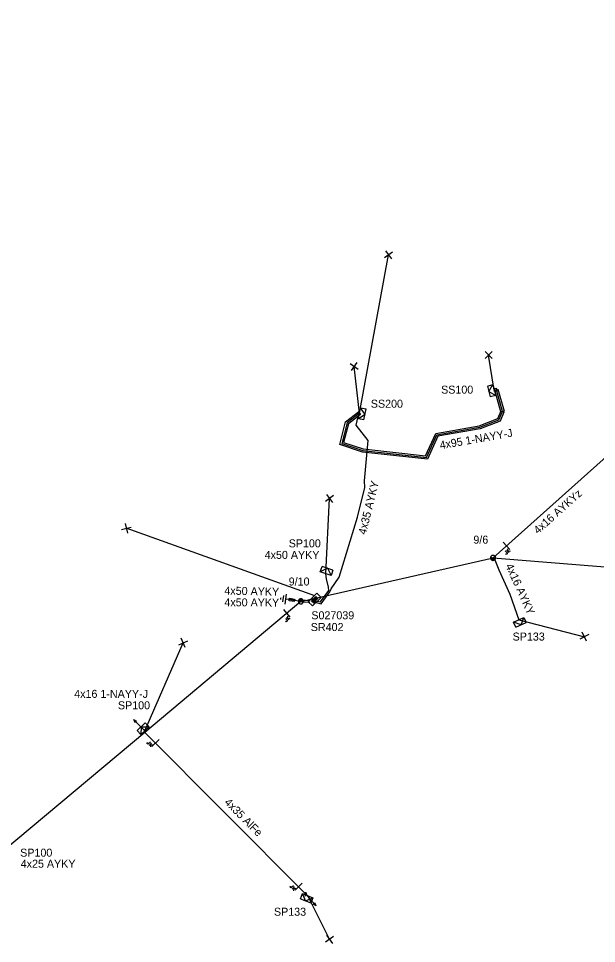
# Model space of a CAD drawing. Extents: x -788458 to -786145, y -1154772 to -1152372.
# Drawn here: x -786525 to -786452.8, y -1153561.6 to -1153446 of the extents above; entities that cross this region are included whole.
import ezdxf

# ---------------------------------------------------------------- set-up
doc = ezdxf.new("R2010")
doc.units = 0
for name, color, linetype in [('Vrstva 1', 7, 'Continuous'), ('Vrstva 12', 7, 'Continuous'), ('Vrstva 13', 7, 'Continuous'), ('Vrstva 14', 7, 'Continuous'), ('Vrstva 15', 7, 'Continuous'), ('Vrstva 16', 7, 'Continuous'), ('Vrstva 18', 7, 'Continuous'), ('Vrstva 2', 7, 'Continuous'), ('Vrstva 20', 7, 'Continuous'), ('Vrstva 28', 7, 'Continuous'), ('Vrstva 29', 7, 'Continuous'), ('Vrstva 30', 7, 'Continuous'), ('Vrstva 31', 7, 'Continuous'), ('Vrstva 33', 7, 'Continuous'), ('Vrstva 34', 7, 'Continuous'), ('Vrstva 4', 7, 'Continuous'), ('Vrstva 5', 7, 'Continuous'), ('Vrstva 52', 7, 'Continuous'), ('Vrstva 53', 7, 'Continuous'), ('Vrstva 54', 7, 'Continuous'), ('Vrstva 55', 7, 'Continuous'), ('Vrstva 59', 7, 'Continuous'), ('Vrstva 6', 7, 'Continuous'), ('Vrstva 8', 7, 'Continuous'), ('Vrstva 9', 7, 'Continuous')]:
    doc.layers.add(name, color=color, linetype=linetype)

# ---------------------------------------------------------------- blocks, each defined once
blk = doc.blocks.new('NN440')
at = {"layer": 'Vrstva 2'}
for points in [[(0.63, 0), (0.63, 0.06), (0.62, 0.13), (0.6, 0.19), (0.58, 0.25), (0.55, 0.31), (0.51, 0.37), (0.47, 0.42), (0.42, 0.46), (0.37, 0.51), (0.32, 0.54), (0.26, 0.57), (0.2, 0.59), (0.13, 0.61), (0.07, 0.62), (0, 0.63), (-0.06, 0.62), (-0.13, 0.61), (-0.19, 0.59), (-0.26, 0.57), (-0.31, 0.54), (-0.37, 0.51), (-0.42, 0.46), (-0.47, 0.42), (-0.51, 0.37), (-0.54, 0.31), (-0.57, 0.25), (-0.6, 0.19), (-0.62, 0.13), (-0.63, 0.06), (-0.63, 0), (-0.63, -0.07), (-0.62, -0.14), (-0.6, -0.2), (-0.57, -0.26), (-0.54, -0.32), (-0.51, -0.37), (-0.47, -0.43), (-0.42, -0.47), (-0.37, -0.51), (-0.31, -0.55), (-0.26, -0.58), (-0.19, -0.6), (-0.13, -0.62), (-0.06, -0.63), (0, -0.63), (0.07, -0.63), (0.13, -0.62), (0.2, -0.6), (0.26, -0.58), (0.32, -0.55), (0.37, -0.51), (0.42, -0.47), (0.47, -0.43), (0.51, -0.37), (0.55, -0.32), (0.58, -0.26), (0.6, -0.2), (0.62, -0.14), (0.63, -0.07), (0.63, 0)], [(-0.63, 0), (0.63, 0)], [(-0.6, -0.18), (0.57, -0.18)], [(-0.51, -0.32), (0.5, -0.32)], [(-0.37, -0.47), (0.35, -0.47)]]:
    blk.add_lwpolyline(points, dxfattribs=at)
blk = doc.blocks.new('NN560')
at = {"layer": 'Vrstva 2'}
for points in [[(2, 0), (1.59, 0.14)], [(0, 0), (2, 0)], [(2, 0), (1.59, -0.13)]]:
    blk.add_lwpolyline(points, dxfattribs=at)
blk = doc.blocks.new('NN840')
at = {"layer": 'Vrstva 15'}
for points in [[(0, 0.62), (0, -0.63)], [(-0.75, -0.71), (-0.75, -0.66)], [(-0.73, -0.76), (-0.75, -0.71)], [(-0.66, -0.8), (-0.73, -0.76)], [(-0.63, -0.8), (-0.66, -0.8)], [(-0.56, -0.76), (-0.63, -0.8)], [(-0.54, -0.71), (-0.56, -0.76)], [(-0.54, -0.38), (-0.54, -0.71)], [(-0.33, -0.38), (-0.33, -0.8)], [(-0.33, -0.64), (-0.13, -0.38)], [(-0.26, -0.56), (-0.09, -0.8)]]:
    blk.add_lwpolyline(points, dxfattribs=at)
blk = doc.blocks.new('NN800')
at = {"layer": 'Vrstva 1'}
for points in [[(-0.44, 0.44), (0.44, -0.44)], [(-0.44, -0.44), (0.44, 0.44)]]:
    blk.add_lwpolyline(points, dxfattribs=at)
blk = doc.blocks.new('NN820')
at = {"layer": 'Vrstva 13'}
for points in [[(0, 0), (0, -1.05)], [(-0.16, -0.81), (0.16, -0.81)], [(-0.16, -1.47), (-0.16, -0.81)], [(0, -1.05), (-0.06, -0.93)], [(0, -1.05), (0.06, -0.93)], [(0.16, -0.81), (0.16, -1.47)], [(0.16, -1.47), (-0.16, -1.47)], [(0, -1.47), (0, -1.87)]]:
    blk.add_lwpolyline(points, dxfattribs=at)
blk = doc.blocks.new('NN620')
at = {"layer": 'Vrstva 8'}
for points in [[(0.75, 0), (-0.75, 0)], [(-0.75, 0), (-0.75, -0.75)], [(0.75, -0.75), (0.75, 0)], [(-0.75, -0.75), (0.75, -0.75)], [(0.37, -0.18), (-0.38, -0.18)], [(-0.38, -0.18), (-0.38, -0.56)], [(-0.38, -0.56), (0.37, -0.56)], [(0.32, -0.23), (-0.33, -0.23)], [(-0.33, -0.23), (-0.33, -0.51)], [(-0.33, -0.51), (0.32, -0.51)], [(0.27, -0.27), (-0.28, -0.27)], [(-0.28, -0.27), (-0.28, -0.46)], [(-0.28, -0.46), (0.27, -0.46)], [(0.23, -0.32), (-0.23, -0.32)], [(-0.23, -0.32), (-0.23, -0.42)], [(-0.23, -0.42), (0.23, -0.42)], [(-0.19, -0.37), (0.19, -0.37)], [(0.23, -0.42), (0.23, -0.32)], [(0.27, -0.46), (0.27, -0.27)], [(0.32, -0.51), (0.32, -0.23)], [(0.37, -0.56), (0.37, -0.18)]]:
    blk.add_lwpolyline(points, dxfattribs=at)
blk = doc.blocks.new('NN630')
at = {"layer": 'Vrstva 9'}
for points in [[(0, -0.7), (-0.7, 0)], [(-0.7, -0.7), (-0.7, 0), (0.7, 0), (0.7, -0.7)], [(-0.7, -0.7), (0.7, -0.7)], [(0, -0.7), (0.7, 0)]]:
    blk.add_lwpolyline(points, dxfattribs=at)
blk = doc.blocks.new('NN810')
at = {"layer": 'Vrstva 14'}
for points in [[(0, -0.64), (0, -1.89)], [(0.63, -1.89), (-0.62, -1.89)], [(0.39, -2.2), (-0.4, -2.2)], [(0, -2.52), (-0.12, -2.52)], [(0.14, -2.52), (0, -2.52)]]:
    blk.add_lwpolyline(points, dxfattribs=at)
blk = doc.blocks.new('NN500')
at = {"layer": 'Vrstva 2'}
for points in [[(0, -0.24), (0.02, -0.23), (0.05, -0.23), (0.07, -0.22), (0.09, -0.22), (0.12, -0.2), (0.14, -0.19), (0.16, -0.18), (0.17, -0.16), (0.19, -0.14), (0.2, -0.12), (0.21, -0.1), (0.22, -0.07), (0.23, -0.05), (0.23, -0.02), (0.23, 0), (0.23, 0.02), (0.23, 0.05), (0.22, 0.07), (0.21, 0.1), (0.2, 0.12), (0.19, 0.14), (0.17, 0.16), (0.16, 0.17), (0.14, 0.19), (0.12, 0.2), (0.09, 0.21), (0.07, 0.22), (0.05, 0.23), (0.02, 0.23), (0, 0.23), (-0.03, 0.23), (-0.05, 0.23), (-0.07, 0.22), (-0.1, 0.21), (-0.12, 0.2), (-0.14, 0.19), (-0.16, 0.17), (-0.18, 0.16), (-0.19, 0.14), (-0.2, 0.12), (-0.22, 0.1), (-0.22, 0.07), (-0.23, 0.05), (-0.23, 0.02), (-0.24, 0), (-0.23, -0.02), (-0.23, -0.05), (-0.22, -0.07), (-0.22, -0.1), (-0.2, -0.12), (-0.19, -0.14), (-0.18, -0.16), (-0.16, -0.18), (-0.14, -0.19), (-0.12, -0.2), (-0.1, -0.22), (-0.07, -0.22), (-0.05, -0.23), (-0.03, -0.23), (0, -0.24)], [(0, -0.24), (0.02, -0.23), (0.05, -0.23), (0.07, -0.22), (0.09, -0.22), (0.12, -0.2), (0.14, -0.19), (0.16, -0.18), (0.17, -0.16), (0.19, -0.14), (0.2, -0.12), (0.21, -0.1), (0.22, -0.07), (0.23, -0.05), (0.23, -0.02), (0.23, 0), (0.23, 0.02), (0.23, 0.05), (0.22, 0.07), (0.21, 0.1), (0.2, 0.12), (0.19, 0.14), (0.17, 0.16), (0.16, 0.17), (0.14, 0.19), (0.12, 0.2), (0.09, 0.21), (0.07, 0.22), (0.05, 0.23), (0.02, 0.23), (0, 0.23), (-0.03, 0.23), (-0.05, 0.23), (-0.07, 0.22), (-0.1, 0.21), (-0.12, 0.2), (-0.14, 0.19), (-0.16, 0.17), (-0.18, 0.16), (-0.19, 0.14), (-0.2, 0.12), (-0.22, 0.1), (-0.22, 0.07), (-0.23, 0.05), (-0.23, 0.02), (-0.24, 0), (-0.23, -0.02), (-0.23, -0.05), (-0.22, -0.07), (-0.22, -0.1), (-0.2, -0.12), (-0.19, -0.14), (-0.18, -0.16), (-0.16, -0.18), (-0.14, -0.19), (-0.12, -0.2), (-0.1, -0.22), (-0.07, -0.22), (-0.05, -0.23), (-0.03, -0.23), (0, -0.24)], [(0, -0.21), (0.02, -0.2), (0.04, -0.2), (0.06, -0.2), (0.08, -0.19), (0.1, -0.18), (0.12, -0.17), (0.14, -0.15), (0.15, -0.14), (0.16, -0.12), (0.18, -0.1), (0.19, -0.08), (0.19, -0.06), (0.2, -0.04), (0.2, -0.02), (0.2, 0), (0.2, 0.02), (0.2, 0.04), (0.19, 0.06), (0.19, 0.08), (0.18, 0.1), (0.16, 0.12), (0.15, 0.14), (0.14, 0.15), (0.12, 0.17), (0.1, 0.18), (0.08, 0.19), (0.06, 0.19), (0.04, 0.2), (0.02, 0.2), (0, 0.2), (-0.02, 0.2), (-0.04, 0.2), (-0.06, 0.19), (-0.08, 0.19), (-0.1, 0.18), (-0.12, 0.17), (-0.14, 0.15), (-0.15, 0.14), (-0.17, 0.12), (-0.18, 0.1), (-0.19, 0.08), (-0.2, 0.06), (-0.2, 0.04), (-0.21, 0.02), (-0.21, 0), (-0.21, -0.02), (-0.2, -0.04), (-0.2, -0.06), (-0.19, -0.08), (-0.18, -0.1), (-0.17, -0.12), (-0.15, -0.14), (-0.14, -0.15), (-0.12, -0.17), (-0.1, -0.18), (-0.08, -0.19), (-0.06, -0.2), (-0.04, -0.2), (-0.02, -0.2), (0, -0.21)], [(0, -0.18), (0.02, -0.18), (0.04, -0.17), (0.05, -0.17), (0.07, -0.16), (0.09, -0.15), (0.1, -0.14), (0.12, -0.13), (0.13, -0.12), (0.14, -0.1), (0.15, -0.09), (0.16, -0.07), (0.17, -0.05), (0.17, -0.04), (0.17, -0.02), (0.17, 0), (0.17, 0.02), (0.17, 0.04), (0.17, 0.05), (0.16, 0.07), (0.15, 0.09), (0.14, 0.1), (0.13, 0.12), (0.12, 0.13), (0.1, 0.14), (0.09, 0.15), (0.07, 0.16), (0.05, 0.17), (0.04, 0.17), (0.02, 0.17), (0, 0.18), (-0.02, 0.17), (-0.04, 0.17), (-0.06, 0.17), (-0.07, 0.16), (-0.09, 0.15), (-0.1, 0.14), (-0.12, 0.13), (-0.13, 0.12), (-0.14, 0.1), (-0.15, 0.09), (-0.16, 0.07), (-0.17, 0.05), (-0.17, 0.04), (-0.18, 0.02), (-0.18, 0), (-0.18, -0.02), (-0.17, -0.04), (-0.17, -0.05), (-0.16, -0.07), (-0.15, -0.09), (-0.14, -0.1), (-0.13, -0.12), (-0.12, -0.13), (-0.1, -0.14), (-0.09, -0.15), (-0.07, -0.16), (-0.06, -0.17), (-0.04, -0.17), (-0.02, -0.18), (0, -0.18)], [(0, -0.15), (0.01, -0.15), (0.03, -0.14), (0.04, -0.14), (0.06, -0.13), (0.07, -0.13), (0.08, -0.12), (0.1, -0.11), (0.11, -0.1), (0.12, -0.09), (0.13, -0.07), (0.13, -0.06), (0.14, -0.05), (0.14, -0.03), (0.14, -0.02), (0.14, 0), (0.14, 0.01), (0.14, 0.03), (0.14, 0.04), (0.13, 0.06), (0.13, 0.07), (0.12, 0.09), (0.11, 0.1), (0.1, 0.11), (0.08, 0.12), (0.07, 0.13), (0.06, 0.13), (0.04, 0.14), (0.03, 0.14), (0.01, 0.14), (0, 0.15), (-0.02, 0.14), (-0.03, 0.14), (-0.05, 0.14), (-0.06, 0.13), (-0.07, 0.13), (-0.09, 0.12), (-0.1, 0.11), (-0.11, 0.1), (-0.12, 0.09), (-0.13, 0.07), (-0.13, 0.06), (-0.14, 0.04), (-0.14, 0.03), (-0.15, 0.01), (-0.15, 0), (-0.15, -0.02), (-0.14, -0.03), (-0.14, -0.05), (-0.13, -0.06), (-0.13, -0.07), (-0.12, -0.09), (-0.11, -0.1), (-0.1, -0.11), (-0.09, -0.12), (-0.07, -0.13), (-0.06, -0.13), (-0.05, -0.14), (-0.03, -0.14), (-0.02, -0.15), (0, -0.15)], [(0, -0.12), (0.01, -0.12), (0.02, -0.11), (0.03, -0.11), (0.05, -0.11), (0.06, -0.1), (0.07, -0.09), (0.08, -0.09), (0.09, -0.08), (0.09, -0.07), (0.1, -0.06), (0.11, -0.05), (0.11, -0.04), (0.11, -0.02), (0.11, -0.01), (0.12, 0), (0.11, 0.01), (0.11, 0.02), (0.11, 0.04), (0.11, 0.05), (0.1, 0.06), (0.09, 0.07), (0.09, 0.08), (0.08, 0.09), (0.07, 0.09), (0.06, 0.1), (0.05, 0.11), (0.03, 0.11), (0.02, 0.11), (0.01, 0.12), (0, 0.12), (-0.01, 0.12), (-0.03, 0.11), (-0.04, 0.11), (-0.05, 0.11), (-0.06, 0.1), (-0.07, 0.09), (-0.08, 0.09), (-0.09, 0.08), (-0.1, 0.07), (-0.1, 0.06), (-0.11, 0.05), (-0.11, 0.04), (-0.12, 0.02), (-0.12, 0.01), (-0.12, 0), (-0.12, -0.01), (-0.12, -0.02), (-0.11, -0.04), (-0.11, -0.05), (-0.1, -0.06), (-0.1, -0.07), (-0.09, -0.08), (-0.08, -0.09), (-0.07, -0.09), (-0.06, -0.1), (-0.05, -0.11), (-0.04, -0.11), (-0.03, -0.11), (-0.01, -0.12), (0, -0.12)], [(0, -0.09), (0.01, -0.09), (0.02, -0.09), (0.03, -0.08), (0.03, -0.08), (0.04, -0.08), (0.05, -0.07), (0.06, -0.07), (0.06, -0.06), (0.07, -0.05), (0.07, -0.04), (0.08, -0.04), (0.08, -0.03), (0.08, -0.02), (0.09, -0.01), (0.09, 0), (0.09, 0.01), (0.08, 0.02), (0.08, 0.03), (0.08, 0.03), (0.07, 0.04), (0.07, 0.05), (0.06, 0.06), (0.06, 0.06), (0.05, 0.07), (0.04, 0.07), (0.03, 0.08), (0.03, 0.08), (0.02, 0.08), (0.01, 0.09), (0, 0.09), (-0.01, 0.09), (-0.02, 0.08), (-0.03, 0.08), (-0.04, 0.08), (-0.04, 0.07), (-0.05, 0.07), (-0.06, 0.06), (-0.07, 0.06), (-0.07, 0.05), (-0.08, 0.04), (-0.08, 0.03), (-0.08, 0.03), (-0.09, 0.02), (-0.09, 0.01), (-0.09, 0), (-0.09, -0.01), (-0.09, -0.02), (-0.08, -0.03), (-0.08, -0.04), (-0.08, -0.04), (-0.07, -0.05), (-0.07, -0.06), (-0.06, -0.07), (-0.05, -0.07), (-0.04, -0.08), (-0.04, -0.08), (-0.03, -0.08), (-0.02, -0.09), (-0.01, -0.09), (0, -0.09)], [(0, -0.06), (0, -0.06), (0.01, -0.06), (0.02, -0.05), (0.02, -0.05), (0.03, -0.05), (0.03, -0.05), (0.04, -0.04), (0.04, -0.04), (0.05, -0.03), (0.05, -0.03), (0.05, -0.02), (0.05, -0.02), (0.05, -0.01), (0.06, -0.01), (0.06, 0), (0.06, 0.01), (0.05, 0.01), (0.05, 0.02), (0.05, 0.02), (0.05, 0.03), (0.05, 0.03), (0.04, 0.04), (0.04, 0.04), (0.03, 0.05), (0.03, 0.05), (0.02, 0.05), (0.02, 0.05), (0.01, 0.06), (0, 0.06), (0, 0.06), (-0.01, 0.06), (-0.01, 0.06), (-0.02, 0.05), (-0.02, 0.05), (-0.03, 0.05), (-0.03, 0.05), (-0.04, 0.04), (-0.04, 0.04), (-0.05, 0.03), (-0.05, 0.03), (-0.05, 0.02), (-0.06, 0.02), (-0.06, 0.01), (-0.06, 0.01), (-0.06, 0), (-0.06, -0.01), (-0.06, -0.01), (-0.06, -0.02), (-0.05, -0.02), (-0.05, -0.03), (-0.05, -0.03), (-0.04, -0.04), (-0.04, -0.04), (-0.03, -0.05), (-0.03, -0.05), (-0.02, -0.05), (-0.02, -0.05), (-0.01, -0.06), (-0.01, -0.06), (0, -0.06)], [(0, -0.03), (0, -0.03), (0, -0.03), (0.01, -0.03), (0.01, -0.03), (0.01, -0.02), (0.02, -0.02), (0.02, -0.02), (0.02, -0.02), (0.02, -0.02), (0.02, -0.01), (0.02, -0.01), (0.03, -0.01), (0.03, -0.01), (0.03, 0), (0.03, 0), (0.03, 0), (0.03, 0.01), (0.03, 0.01), (0.02, 0.01), (0.02, 0.01), (0.02, 0.02), (0.02, 0.02), (0.02, 0.02), (0.02, 0.02), (0.01, 0.02), (0.01, 0.02), (0.01, 0.03), (0, 0.03), (0, 0.03), (0, 0.03), (0, 0.03), (-0.01, 0.03), (-0.01, 0.03), (-0.01, 0.02), (-0.02, 0.02), (-0.02, 0.02), (-0.02, 0.02), (-0.02, 0.02), (-0.02, 0.02), (-0.03, 0.01), (-0.03, 0.01), (-0.03, 0.01), (-0.03, 0.01), (-0.03, 0), (-0.03, 0), (-0.03, 0), (-0.03, -0.01), (-0.03, -0.01), (-0.03, -0.01), (-0.03, -0.01), (-0.02, -0.02), (-0.02, -0.02), (-0.02, -0.02), (-0.02, -0.02), (-0.02, -0.02), (-0.01, -0.03), (-0.01, -0.03), (-0.01, -0.03), (0, -0.03), (0, -0.03)], [(0.23, 0), (0.7, 0)]]:
    blk.add_lwpolyline(points, dxfattribs=at)

msp = doc.modelspace()

# ---------------------------------------------------------------- linework, layer by layer
at = {"layer": 'Vrstva 1'}
for points in [[(-786489.69, -1153518.84), (-786509.16, -1153535.21), (-786526.82, -1153550.01), (-786583.29, -1153546.79), (-786577.19, -1153510.6), (-786570.4, -1153472.16), (-786563.85, -1153433.39), (-786557.73, -1153395.36), (-786551.92, -1153358.3), (-786545.97, -1153321.74)], [(-786489.69, -1153518.84), (-786465.68, -1153513.4), (-786435.17, -1153515.87), (-786408.35, -1153517.77)]]:
    msp.add_lwpolyline(points, dxfattribs=at)
at = {"layer": 'Vrstva 20'}
for points in [[(-786465.56, -1153492.23), (-786465.29, -1153492.19), (-786465.23, -1153492.59), (-786465.5, -1153492.63)], [(-786464.69, -1153495.15), (-786465.45, -1153492.44), (-786465.07, -1153492.34), (-786464.31, -1153495.05)], [(-786482.24, -1153495.49), (-786483.74, -1153496.66), (-786484.35, -1153498.99), (-786481.92, -1153499.79), (-786474.12, -1153500.64), (-786472.85, -1153497.85), (-786467.4, -1153496.9), (-786465.1, -1153495.98), (-786464.68, -1153495.02), (-786464.32, -1153495.18), (-786464.8, -1153496.3), (-786467.3, -1153497.28), (-786472.57, -1153498.21), (-786473.88, -1153501.06), (-786482, -1153500.19), (-786484.83, -1153499.25), (-786484.1, -1153496.42), (-786482.48, -1153495.17)]]:
    msp.add_lwpolyline(points, close=True, dxfattribs=at)
at = {"layer": 'Vrstva 4'}
msp.add_lwpolyline([(-786509.16, -1153535.21), (-786489.09, -1153555.38), (-786488.84, -1153555.62)], dxfattribs=at)
at = {"layer": 'Vrstva 5'}
for points in [[(-786482.36, -1153495.33), (-786483.92, -1153496.54), (-786484.59, -1153499.12), (-786481.96, -1153499.99), (-786474, -1153500.85), (-786472.71, -1153498.03), (-786467.35, -1153497.09), (-786464.95, -1153496.14), (-786464.5, -1153495.1), (-786465.26, -1153492.39), (-786465.53, -1153492.43)], [(-786487.78, -1153518.97), (-786487.15, -1153519.13), (-786486.07, -1153517.66), (-786485.91, -1153517.26), (-786484.92, -1153515.82), (-786482.61, -1153508.3), (-786481.7, -1153504.6), (-786481.72, -1153503.79), (-786481.29, -1153498.73), (-786482.8, -1153496.82), (-786482.55, -1153495.74), (-786482.36, -1153495.33)], [(-786488.53, -1153518.77), (-786489.12, -1153518.75), (-786489.55, -1153518.73), (-786489.69, -1153518.84)], [(-786488.58, -1153518.97), (-786489.53, -1153518.94), (-786489.69, -1153518.84)]]:
    msp.add_lwpolyline(points, dxfattribs=at)
at = {"layer": 'Vrstva 52'}
for points in [[(-786465.68, -1153513.4), (-786465.45, -1153513.65), (-786464.96, -1153514.88), (-786463.58, -1153517.93), (-786462.48, -1153521.15)], [(-786487.62, -1153518.81), (-786487.23, -1153518.91), (-786486.18, -1153517.47), (-786486.25, -1153517.08), (-786486.47, -1153516.01), (-786486.59, -1153515.38)]]:
    msp.add_lwpolyline(points, dxfattribs=at)
at = {"layer": 'Vrstva 54'}
msp.add_lwpolyline([(-786465.68, -1153513.4), (-786449.16, -1153498.66), (-786449, -1153498.89)], dxfattribs=at)
at = {"layer": 'Vrstva 59'}
for points in [[(-786482.36, -1153495.33), (-786478.75, -1153475.55)], [(-786465.53, -1153492.43), (-786466.24, -1153488.06)], [(-786482.36, -1153495.33), (-786483.05, -1153489.47)], [(-786486.59, -1153515.38), (-786486.12, -1153505.99)], [(-786487.93, -1153518.17), (-786511.5, -1153509.71)], [(-786462.48, -1153521.15), (-786454.28, -1153523.26)], [(-786509.16, -1153535.01), (-786504.38, -1153524.02)], [(-786488.84, -1153555.62), (-786486.11, -1153561.09)]]:
    msp.add_lwpolyline(points, dxfattribs=at)
at = {"layer": 'Vrstva 8'}
msp.add_lwpolyline([(-786509.16, -1153535.21), (-786509.16, -1153535.01)], dxfattribs=at)

# ---------------------------------------------------------------- block references
at = {"layer": 'Vrstva 13', "yscale": 0.5}
for name, p, xscale, rotation in [('NN440', (-786465.68, -1153513.4), 0.5, -13.829819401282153), ('NN440', (-786489.69, -1153518.84), 0.5, -142.00139163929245), ('NN500', (-786509.16, -1153535.01), 0.5, 136.7389999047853), ('NN500', (-786489.09, -1153555.38), 0.49999999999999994, -107.399000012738)]:
    msp.add_blockref(name, p, dxfattribs=dict(at, xscale=xscale, rotation=rotation))
at = {"layer": 'Vrstva 13'}
for p, rotation in [((-786509.16, -1153535.01), 135.71013331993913), ((-786489.09, -1153555.38), -49.68320555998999)]:
    msp.add_blockref('NN560', p, dxfattribs=dict(at, rotation=rotation))
at = {"layer": 'Vrstva 15', "rotation": -98.69812771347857}
msp.add_blockref('NN810', (-786489.69, -1153518.84), dxfattribs=at)
at = {"layer": 'Vrstva 16', "rotation": -98.69922221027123}
msp.add_blockref('NN820', (-786489.69, -1153518.84), dxfattribs=at)
at = {"layer": 'Vrstva 18'}
for p, rotation in [((-786464, -1153511.9), 41.74099578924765), ((-786491.46, -1153520.33), 40.0564745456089), ((-786507.84, -1153536.54), -45.14238484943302), ((-786489.97, -1153554.5), -45.14238484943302)]:
    msp.add_blockref('NN840', p, dxfattribs=dict(at, rotation=rotation))
at = {"layer": 'Vrstva 28', "rotation": -135}
msp.add_blockref('NN620', (-786487.7, -1153518.89), dxfattribs=at)
at = {"layer": 'Vrstva 31'}
for p, rotation in [((-786465.53, -1153492.43), -75.59778379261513), ((-786482.36, -1153495.33), 78.66098919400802), ((-786486.59, -1153515.38), 162.40757535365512), ((-786462.48, -1153521.15), 24.63011890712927), ((-786509.16, -1153535.01), -136.10881209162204), ((-786488.84, -1153555.62), -21.729789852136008)]:
    msp.add_blockref('NN630', p, dxfattribs=dict(at, rotation=rotation))
at = {"layer": 'Vrstva 34'}
for p, rotation in [((-786478.75, -1153475.55), -98.71133333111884), ((-786483.05, -1153489.47), -81.50046110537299), ((-786486.12, -1153505.99), -98.07459999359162), ((-786511.5, -1153509.71), -31.111094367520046), ((-786504.38, -1153524.02), 68.56581666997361), ((-786454.28, -1153523.26), 162.2861055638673), ((-786486.11, -1153561.09), -99.95051670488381)]:
    msp.add_blockref('NN800', p, dxfattribs=dict(at, rotation=rotation))
msp.add_blockref('NN800', (-786466.24, -1153488.06), dxfattribs=at)

# ---------------------------------------------------------------- texts
at = {"layer": 'Vrstva 12'}
for s, p in [('9/6', (-786468.14, -1153511.63)), ('9/10', (-786491.21, -1153516.86))]:
    msp.add_text(s, height=1, dxfattribs=at).set_placement(p)
at = {"layer": 'Vrstva 29'}
msp.add_text('S027039', height=1, dxfattribs=at).set_placement((-786488.38, -1153521.08))
at = {"layer": 'Vrstva 30'}
msp.add_text('SR402', height=1, dxfattribs=at).set_placement((-786488.45, -1153522.55))
at = {"layer": 'Vrstva 33'}
for s, p in [('SS100', (-786472.17, -1153492.88)), ('SS200', (-786480.95, -1153494.64)), ('SP100', (-786491.21, -1153512.09)), ('SP133', (-786463.24, -1153523.74)), ('SP100', (-786512.54, -1153532.33)), ('SP100', (-786524.75, -1153550.75)), ('SP133', (-786493.05, -1153558.13))]:
    msp.add_text(s, height=1, dxfattribs=at).set_placement(p)
at = {"layer": 'Vrstva 53'}
msp.add_text('4x35 AlFe', height=1, rotation=314.783, dxfattribs=at).set_placement((-786499.32, -1153544.04))
at = {"layer": 'Vrstva 54'}
for s, rotation, p in [('4x50 AYKY', 359.935, (-786494.21, -1153513.53)), ('4x16 AYKY', 294.345, (-786464.16, -1153514.38))]:
    msp.add_text(s, height=1, rotation=rotation, dxfattribs=at).set_placement(p)
msp.add_text('4x25 AYKY', height=1, dxfattribs=at).set_placement((-786524.68, -1153552.13))
at = {"layer": 'Vrstva 55'}
msp.add_text('4x16 AYKYz', height=1, rotation=41.741, dxfattribs=at).set_placement((-786460.08, -1153510.49))
msp.add_text('4x16 1-NAYY-J', height=1, dxfattribs=at).set_placement((-786518, -1153530.9))
at = {"layer": 'Vrstva 6'}
for s, rotation, p in [('4x95 1-NAYY-J', 9.947, (-786472.26, -1153499.83)), ('4x35 AYKY', 76.183, (-786481.57, -1153510.57)), ('4x50 AYKY', 358.561, (-786499.25, -1153517.98)), ('4x50 AYKY', 359.661, (-786499.24, -1153519.45))]:
    msp.add_text(s, height=1, rotation=rotation, dxfattribs=at).set_placement(p)

doc.saveas('drawing.dxf')
